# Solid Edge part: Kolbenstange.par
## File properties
Author: ahadarics
Last saved by: ahadarics
Revision: 77
Sűrűség: 0,000 kg/m^3
Pontosság: 0,990
Username: ahadarics
Dokumentum tartalom típus: 0
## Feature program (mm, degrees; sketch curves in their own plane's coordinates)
base feature "unnamed BaseFeature 1"
thread "unnamed Thread 1"
chamfer "Letörés_1" setback 0.7
sketch for "Kihúzás_1" plane through (57.5, 0, 0) normal (1, 0, 0) x-axis (0, 1, 0)
  circle centre (0, 0) radius 12.5
extrude "Kihúzás_1" add finite 27 along -normal
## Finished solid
Body 1: solid body, 13 faces, 23 edges, 12 vertices.
  Faces by surface: plane 9, cylinder 3, cone 1
  Edges by curve: line 12, circle 11
Bounding box of the edges (mm): 119.500 x 25.000 x 25.000, from (-62, -12.5, -12.5) to (57.5, 12.5, 12.5).
Cylindrical faces by radius (mm): R5 x2, R12.5 x1
Conical faces (half-angle, radius in mm at the cone's reference point): 45 deg R4.3 x1
Planar faces by outward normal: +x 3, +z 1, -x 4, -z 1
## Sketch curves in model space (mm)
circle centre (57.5, 0, 0) radius 12.5
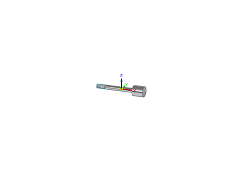
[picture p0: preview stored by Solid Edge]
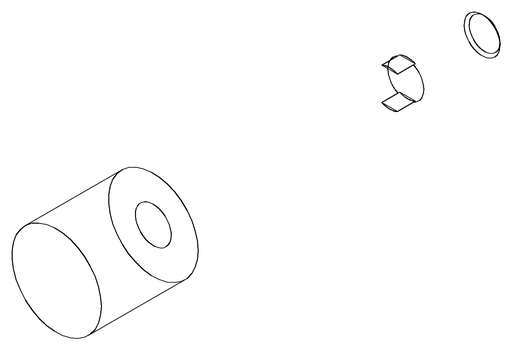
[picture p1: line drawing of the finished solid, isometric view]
